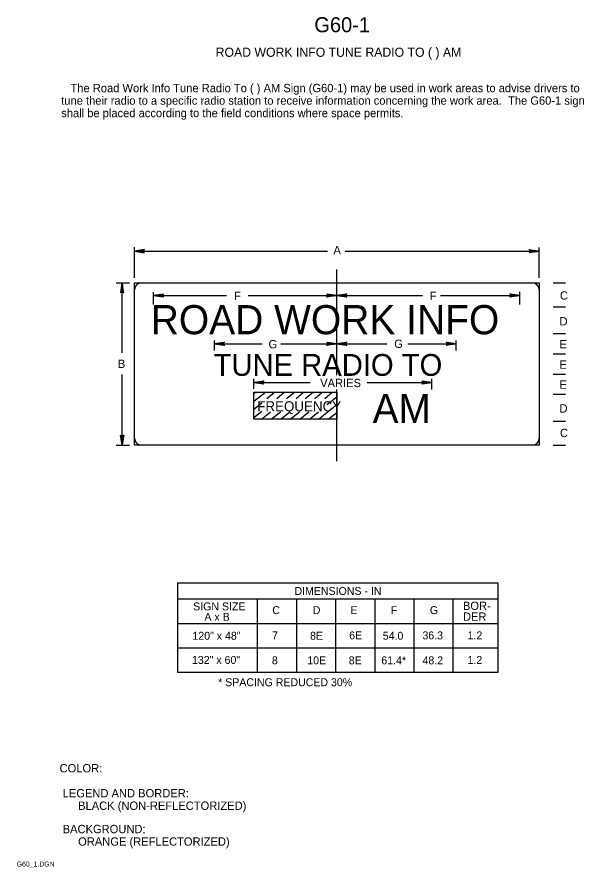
# Model space of a CAD drawing. Extents: x 0.012 to 0.183, y 0.004 to 0.259.
import ezdxf

# ---------------------------------------------------------------- set-up
doc = ezdxf.new("R2010")
doc.units = 0
doc.layers.add('1', color=7, linetype='Continuous')
doc.layers.add('3', color=7, linetype='Continuous')

# ---------------------------------------------------------------- blocks, each defined once
blk = doc.blocks.new('RARROW')
at = {"layer": '3'}
blk.add_lwpolyline([(-2.2695, 0.285), (-2.184875, 0.12075), (0, 0), (-2.2695, 0.285), (-2.38575, 0.384625), (0, 0), (-2.183125, -0.108), (-2.262875, -0.2705), (0, 0), (-2.38575, -0.379125), (-2.262875, -0.2705)], dxfattribs=at)

msp = doc.modelspace()

# ---------------------------------------------------------------- linework, layer by layer
at = {"layer": '1'}
for p, q in [((0.04763, 0.181), (0.04763, 0.19025)), ((0.04763, 0.189), (0.10562, 0.189)), ((0.11088, 0.189), (0.16912, 0.189)), ((0.16912, 0.181), (0.16912, 0.19013)), ((0.10837, 0.15188), (0.10837, 0.1835)), ((0.04213, 0.1795), (0.04612, 0.1795)), ((0.04388, 0.1585), (0.04388, 0.1795)), ((0.04767, 0.17747), (0.04767, 0.1795)), ((0.04767, 0.1795), (0.04969, 0.1795)), ((0.04969, 0.1795), (0.16917, 0.1795)), ((0.16917, 0.1795), (0.16917, 0.13087)), ((0.17338, 0.1795), (0.177, 0.1795)), ((0.04767, 0.13087), (0.04767, 0.17747)), ((0.05337, 0.173), (0.05337, 0.17675)), ((0.16337, 0.173), (0.16337, 0.17688)), ((0.05337, 0.17575), (0.07525, 0.17575)), ((0.08175, 0.17575), (0.10837, 0.17575)), ((0.10837, 0.17575), (0.13412, 0.17575)), ((0.1395, 0.17575), (0.16337, 0.17575)), ((0.17338, 0.17238), (0.177, 0.17238)), ((0.17338, 0.16437), (0.177, 0.16437)), ((0.07163, 0.15925), (0.07163, 0.16225)), ((0.07163, 0.16125), (0.086, 0.16125)), ((0.09162, 0.16125), (0.10837, 0.16125)), ((0.10837, 0.16125), (0.12337, 0.16125)), ((0.12975, 0.16125), (0.14425, 0.16125)), ((0.14425, 0.15925), (0.14425, 0.16225)), ((0.17338, 0.15825), (0.177, 0.15825)), ((0.04388, 0.13087), (0.04388, 0.152)), ((0.0835, 0.14775), (0.0835, 0.15075)), ((0.13687, 0.1475), (0.13687, 0.15075)), ((0.17338, 0.15213), (0.177, 0.15213)), ((0.0835, 0.14963), (0.10038, 0.14963)), ((0.1175, 0.14963), (0.13687, 0.14963)), ((0.0835, 0.14625), (0.084, 0.14675)), ((0.0835, 0.144), (0.087, 0.14675)), ((0.08738, 0.14488), (0.08962, 0.14675)), ((0.09037, 0.14488), (0.09262, 0.14675)), ((0.09325, 0.14488), (0.09563, 0.14675)), ((0.09613, 0.14488), (0.09838, 0.14675)), ((0.09888, 0.14488), (0.10125, 0.14675)), ((0.10175, 0.14488), (0.104, 0.14675)), ((0.10475, 0.14488), (0.107, 0.14675)), ((0.10837, 0.126), (0.10837, 0.1475)), ((0.17338, 0.14613), (0.177, 0.14613)), ((0.0835, 0.14163), (0.08588, 0.1435)), ((0.10537, 0.143), (0.10837, 0.14538)), ((0.0835, 0.13912), (0.08588, 0.141)), ((0.08575, 0.13862), (0.0885, 0.14088)), ((0.08862, 0.13862), (0.0915, 0.14088)), ((0.09162, 0.13862), (0.09425, 0.14088)), ((0.09438, 0.13862), (0.09713, 0.14088)), ((0.09725, 0.13862), (0.1, 0.14088)), ((0.10013, 0.13862), (0.10288, 0.14088)), ((0.10288, 0.13862), (0.10837, 0.143)), ((0.10575, 0.13862), (0.10837, 0.14062)), ((0.17338, 0.138), (0.177, 0.138)), ((0.04213, 0.13087), (0.04612, 0.13087)), ((0.16917, 0.13087), (0.04767, 0.13087)), ((0.17338, 0.13087), (0.177, 0.13087))]:
    msp.add_line(p, q, dxfattribs=at)
msp.add_lwpolyline([(0.0835, 0.14675), (0.10837, 0.14675), (0.10837, 0.13862), (0.0835, 0.13862)], close=True, dxfattribs=at)
for centre, start, end in [((0.04969, 0.17747), 90, 180), ((0.16714, 0.17747), 359.3226, 89.3226), ((0.04969, 0.1329), 180, 270), ((0.16714, 0.1329), 270, 0)]:
    msp.add_arc(centre, 0.00202, start, end, dxfattribs=at)
at = {"layer": '3'}
for p, q in [((0.0605, 0.0895), (0.15675, 0.0895)), ((0.0605, 0.0895), (0.0605, 0.06263)), ((0.15675, 0.0895), (0.15675, 0.06263)), ((0.15675, 0.08463), (0.0605, 0.08463)), ((0.08451, 0.08456), (0.08451, 0.06263)), ((0.09625, 0.08463), (0.09625, 0.06263)), ((0.108, 0.08463), (0.108, 0.06263)), ((0.108, 0.08463), (0.108, 0.07125)), ((0.11975, 0.08463), (0.11975, 0.06263)), ((0.1315, 0.08463), (0.1315, 0.06263)), ((0.14326, 0.08456), (0.14326, 0.06263)), ((0.15675, 0.07725), (0.0605, 0.07725)), ((0.15675, 0.06988), (0.0605, 0.06988)), ((0.15675, 0.06263), (0.0605, 0.06263))]:
    msp.add_line(p, q, dxfattribs=at)

# ---------------------------------------------------------------- block references
at = {"layer": '3', "xscale": 0.0012574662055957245}
for p, yscale, rotation in [((0.04763, 0.189), -0.001309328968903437, -180), ((0.04388, 0.1795), -0.001309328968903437, 90.00000000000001), ((0.05337, 0.17575), 0.001309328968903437, 180), ((0.10837, 0.17575), 0.001309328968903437, 180), ((0.07163, 0.16125), 0.001309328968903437, 180), ((0.10837, 0.16125), 0.001309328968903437, 180), ((0.0835, 0.14963), 0.001309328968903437, 180), ((0.04388, 0.13087), 0.001309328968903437, -90.00000000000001)]:
    msp.add_blockref('RARROW', p, dxfattribs=dict(at, yscale=yscale, rotation=rotation))
at = {"layer": '3', "xscale": 0.0012574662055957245, "yscale": 0.001309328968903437}
for p in [(0.16912, 0.189), (0.10837, 0.17575), (0.16337, 0.17575), (0.10837, 0.16125), (0.14425, 0.16125), (0.13687, 0.14963)]:
    msp.add_blockref('RARROW', p, dxfattribs=at)

# ---------------------------------------------------------------- texts
at = {"layer": '1'}
for s, height, p in [('G60-1', 0.0045, (0.10163, 0.25475)), ('ROAD WORK INFO TUNE RADIO TO ( ) AM', 0.0027503, (0.072, 0.24738)), ('A', 0.0025, (0.10737, 0.18813)), ('F', 0.0025, (0.0775, 0.17438)), ('F', 0.0025, (0.13625, 0.17438)), ('C', 0.0025, (0.17538, 0.1745)), ('ROAD WORK INFO', 0.0087502, (0.0525, 0.16412)), ('D', 0.0025, (0.17525, 0.16675)), ('G', 0.0025, (0.08788, 0.15988)), ('G', 0.0025, (0.12563, 0.16)), ('E', 0.0025, (0.17525, 0.15988)), ('B', 0.0025, (0.04263, 0.154)), ('TUNE RADIO TO', 0.0065557, (0.07138, 0.15163)), ('E', 0.0025, (0.17525, 0.15375)), ('VARIES', 0.0025, (0.10338, 0.14825)), ('E', 0.0025, (0.17525, 0.14775)), ('AM', 0.008697, (0.11913, 0.1375)), ('FREQUENCY', 0.003, (0.0845, 0.141)), ('D', 0.0025, (0.17525, 0.14062)), ('C', 0.0025, (0.17538, 0.13325)), ('COLOR:', 0.0025, (0.02513, 0.03263)), (' LEGEND AND BORDER:', 0.0024998, (0.02513, 0.02513)), ('      BLACK (NON-REFLECTORIZED)', 0.0024998, (0.02513, 0.02138)), (' BACKGROUND:', 0.0024998, (0.02513, 0.01438)), ('      ORANGE (REFLECTORIZED)', 0.0024998, (0.02513, 0.01063)), ('G60_1.DGN', 0.0015, (0.01225, 0.00438))]:
    msp.add_text(s, height=height, dxfattribs=at).set_placement(p)
at = {"layer": '3'}
for s, height, p in [('   The Road Work Info Tune Radio To ( ) AM Sign (G60-1) may be used in work areas to advise drivers to', 0.00249975, (0.02563, 0.23675)), ('tune their radio to a specific radio station to receive information concerning the work area.  The G60-1 sign', 0.00249975, (0.02563, 0.233)), ('shall be placed according to the field conditions where space permits.', 0.0024998, (0.02563, 0.22925)), ('DIMENSIONS - IN', 0.0023752, (0.09567, 0.08588)), ('SIGN SIZE', 0.002375, (0.06525, 0.08125)), ('C', 0.00238, (0.089, 0.08013)), ('D', 0.00238, (0.10116, 0.08013)), ('E', 0.00238, (0.1125, 0.08013)), ('F', 0.00238, (0.12456, 0.08013)), ('G', 0.00238, (0.13633, 0.08013)), ('BOR-', 0.0025, (0.14625, 0.08138)), ('A x B', 0.002375, (0.06863, 0.07812)), ('DER', 0.0025, (0.14625, 0.07812)), ('120" x 48"', 0.002375, (0.06503, 0.07244)), ('7', 0.00238, (0.08893, 0.07256)), ('8E', 0.002375, (0.10035, 0.07244)), ('6E', 0.002375, (0.1121, 0.07256)), ('54.0', 0.002375, (0.12218, 0.07244)), ('36.3', 0.002375, (0.13409, 0.07256)), ('1.2', 0.002375, (0.14764, 0.07256)), ('132" x 60"', 0.002375, (0.0649, 0.06519)), ('8', 0.00238, (0.08888, 0.06506)), ('10E', 0.002375, (0.0995, 0.06506)), ('8E', 0.002375, (0.11197, 0.06506)), ('61.4*', 0.002375, (0.12175, 0.06506)), ('48.2', 0.002375, (0.13411, 0.06506)), ('1.2', 0.002375, (0.14764, 0.06519)), ('* SPACING REDUCED 30%', 0.0023752, (0.07275, 0.0585))]:
    msp.add_text(s, height=height, dxfattribs=at).set_placement(p)

doc.saveas('drawing.dxf')
